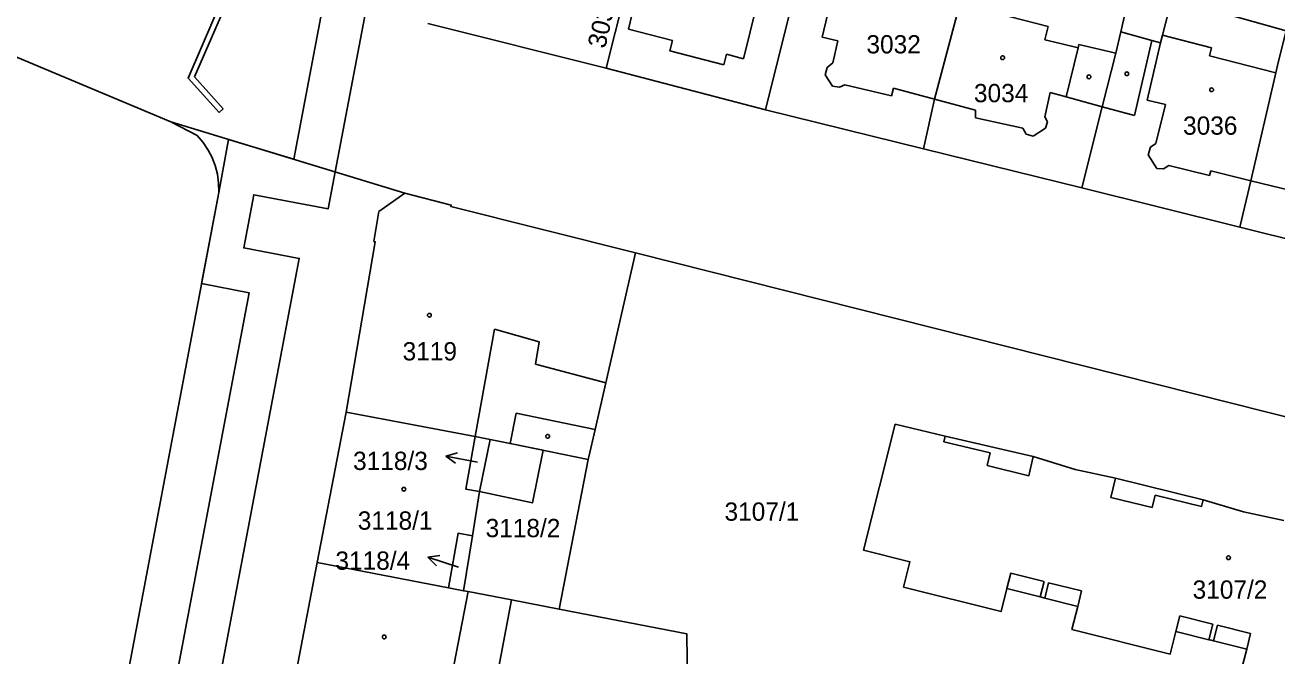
# Model space of a CAD drawing. Extents: x -756746 to -753363, y -1166406 to -1161727.
# Drawn here: x -755238.8 to -755122.4, y -1165407.1 to -1165348.4 of the extents above; entities that cross this region are included whole.
import ezdxf

# ---------------------------------------------------------------- set-up
doc = ezdxf.new("R2010")
doc.units = 0
for name, color, linetype in [('Hranice parcel', 7, 'Continuous'), ('Parcelní čísla', 7, 'Continuous'), ('Pop  PČ popisy', 7, 'Continuous'), ('Vnitřní kresba', 7, 'Continuous'), ('Věcná břemena k části', 7, 'Continuous'), ('Značky budov', 7, 'Continuous')]:
    doc.layers.add(name, color=color, linetype=linetype)

msp = doc.modelspace()

# ---------------------------------------------------------------- linework, layer by layer
at = {"layer": 'Hranice parcel'}
for p, q in [((-755287.52, -1165331.34), (-755225.27, -1165357.44)), ((-755184.78, -1165352.45), (-755180.27, -1165334.69)), ((-755136.91, -1165349.06), (-755136.02, -1165345.27)), ((-755201.37, -1165348.31), (-755184.78, -1165352.45)), ((-755184.78, -1165352.45), (-755169.95, -1165356.34)), ((-755169.95, -1165356.34), (-755155.26, -1165359.95)), ((-755203.5, -1165364.07), (-755225.27, -1165357.44)), ((-755225.27, -1165357.44), (-755222.8, -1165358.71)), ((-755155.26, -1165359.95), (-755140.53, -1165363.57)), ((-755220.8, -1165364.01), (-755235.29, -1165440.63)), ((-755140.53, -1165363.57), (-755125.82, -1165367.24)), ((-755125.82, -1165367.24), (-755111.07, -1165370.94)), ((-755067.44, -1165398.51), (-755182.05, -1165369.63)), ((-755211.66, -1165398.42), (-755208.96, -1165384.45)), ((-755208.96, -1165384.45), (-755196.95, -1165386.71)), ((-755196.95, -1165386.71), (-755195.56, -1165386.99)), ((-755195.56, -1165386.99), (-755196.55, -1165391.83)), ((-755153.23, -1165386.66), (-755145.04, -1165388.58)), ((-755186.44, -1165388.84), (-755189.13, -1165402.77)), ((-755137.4, -1165390.57), (-755129.23, -1165392.58)), ((-755197.2, -1165395.95), (-755196.55, -1165391.83)), ((-755197.2, -1165395.95), (-755198.03, -1165401.05)), ((-755211.66, -1165398.42), (-755214.3, -1165412.31)), ((-755199.44, -1165400.78), (-755211.66, -1165398.42)), ((-755198.03, -1165401.05), (-755199.44, -1165400.78)), ((-755196.19, -1165415.73), (-755193.58, -1165401.91)), ((-755189.13, -1165402.77), (-755193.58, -1165401.91))]:
    msp.add_line(p, q, dxfattribs=at)
for points in [[(-755155.26, -1165359.95), (-755154.24, -1165355.34), (-755151.87, -1165346.47), (-755151.6, -1165345.43), (-755150.66, -1165341.53)], [(-755121.51, -1165348.98), (-755132.14, -1165345.97), (-755133.02, -1165349.37), (-755133.22, -1165350.11), (-755134.01, -1165349.88), (-755136.91, -1165349.06)], [(-755169.95, -1165356.34), (-755167.78, -1165347.62), (-755167.55, -1165346.71)], [(-755140.53, -1165363.57), (-755138.62, -1165356.06), (-755137.35, -1165351.07), (-755136.91, -1165349.06)], [(-755125.82, -1165367.24), (-755124.82, -1165362.92), (-755122.49, -1165352.89), (-755122.26, -1165351.91), (-755121.51, -1165348.98)], [(-755222.8, -1165358.71), (-755222.25, -1165359.36), (-755221.78, -1165360.07), (-755221.45, -1165360.7), (-755221.14, -1165361.49), (-755220.93, -1165362.32), (-755220.82, -1165363.16), (-755220.8, -1165364.01)], [(-755203.5, -1165364.07), (-755205.9, -1165365.79), (-755206.39, -1165368.56), (-755206.24, -1165368.59), (-755208.96, -1165384.45)], [(-755182.05, -1165369.63), (-755199.21, -1165365.32), (-755199.18, -1165365.18), (-755203.5, -1165364.07)], [(-755182.05, -1165369.63), (-755184.81, -1165381.71), (-755185.8, -1165386.05), (-755186.39, -1165388.6), (-755186.44, -1165388.84)], [(-755147.5, -1165400.85), (-755148.04, -1165402.99), (-755157.11, -1165400.71), (-755156.52, -1165398.36), (-755160.83, -1165397.28), (-755157.88, -1165385.57), (-755153.23, -1165386.66)], [(-755196.55, -1165391.83), (-755197.82, -1165391.61), (-755196.95, -1165386.71)], [(-755195.56, -1165386.99), (-755193.71, -1165387.37), (-755186.44, -1165388.84)], [(-755145.04, -1165388.58), (-755141.16, -1165389.76), (-755137.4, -1165390.57)], [(-755129.23, -1165392.58), (-755125.48, -1165393.7), (-755121.74, -1165394.52)], [(-755199.44, -1165400.78), (-755198.54, -1165395.71), (-755197.2, -1165395.95)], [(-755193.58, -1165401.91), (-755197.6, -1165401.13), (-755198.03, -1165401.05)], [(-755140.91, -1165402.53), (-755143.98, -1165401.75), (-755144.19, -1165401.69), (-755144.39, -1165401.63), (-755147.5, -1165400.85)], [(-755189.13, -1165402.77), (-755177.26, -1165405.07), (-755177.17, -1165412.37)], [(-755131.77, -1165404.84), (-755132.3, -1165406.94), (-755141.44, -1165404.64), (-755140.91, -1165402.53)], [(-755125.19, -1165406.48), (-755128.29, -1165405.7), (-755128.49, -1165405.66), (-755128.7, -1165405.6), (-755131.77, -1165404.84)], [(-755116.11, -1165408.75), (-755116.64, -1165410.87), (-755125.72, -1165408.59), (-755125.19, -1165406.48)]]:
    msp.add_lwpolyline(points, dxfattribs=at)
at = {"layer": 'Pop  PČ popisy'}
for p, q in [((-755199.67, -1165388.52), (-755198.59, -1165388.22)), ((-755196.72, -1165389.09), (-755199.67, -1165388.52)), ((-755199.67, -1165388.52), (-755198.78, -1165389.2)), ((-755201.35, -1165397.93), (-755200.25, -1165397.77)), ((-755198.5, -1165398.86), (-755201.35, -1165397.93)), ((-755201.35, -1165397.93), (-755200.56, -1165398.72))]:
    msp.add_line(p, q, dxfattribs=at)
at = {"layer": 'Vnitřní kresba'}
for p, q in [((-755179.86, -1165337.08), (-755182.7, -1165348.82)), ((-755171.99, -1165351.57), (-755170.74, -1165346.56)), ((-755143.67, -1165348.57), (-755151.87, -1165346.47)), ((-755164.17, -1165347.48), (-755164.67, -1165349.56)), ((-755182.7, -1165348.82), (-755178.6, -1165349.87)), ((-755143.96, -1165349.82), (-755143.67, -1165348.57)), ((-755178.6, -1165349.87), (-755178.85, -1165350.84)), ((-755164.67, -1165349.56), (-755163.21, -1165349.92)), ((-755163.21, -1165349.92), (-755163.7, -1165351.95)), ((-755142.51, -1165350.17), (-755143.96, -1165349.82)), ((-755135.62, -1165356.84), (-755134.01, -1165349.88)), ((-755133.22, -1165350.11), (-755134.45, -1165355.42)), ((-755128.47, -1165350.55), (-755133.02, -1165349.37)), ((-755178.85, -1165350.84), (-755173.81, -1165352.13)), ((-755173.81, -1165352.13), (-755173.56, -1165351.16)), ((-755173.56, -1165351.16), (-755171.99, -1165351.57)), ((-755140.87, -1165350.55), (-755142.51, -1165350.17)), ((-755141.98, -1165355.13), (-755140.87, -1165350.55)), ((-755140.87, -1165350.55), (-755140.8, -1165350.26)), ((-755140.8, -1165350.26), (-755137.35, -1165351.07)), ((-755128.66, -1165351.29), (-755128.47, -1165350.55)), ((-755164.22, -1165352.39), (-755164.4, -1165353.07)), ((-755163.7, -1165351.95), (-755164.22, -1165352.39)), ((-755122.49, -1165352.89), (-755128.66, -1165351.29)), ((-755164.4, -1165353.07), (-755163.72, -1165354.14)), ((-755163.72, -1165354.14), (-755163.07, -1165354.23)), ((-755163.07, -1165354.23), (-755162.56, -1165354.01)), ((-755162.56, -1165354.01), (-755158.24, -1165355.02)), ((-755158.24, -1165355.02), (-755158.05, -1165354.32)), ((-755158.05, -1165354.32), (-755154.24, -1165355.34)), ((-755143.97, -1165356.99), (-755143.48, -1165354.71)), ((-755143.48, -1165354.71), (-755141.98, -1165355.13)), ((-755154.24, -1165355.34), (-755150.43, -1165356.36)), ((-755141.98, -1165355.13), (-755138.62, -1165356.06)), ((-755134.45, -1165355.42), (-755132.74, -1165355.84)), ((-755132.74, -1165355.84), (-755133.63, -1165359.47)), ((-755150.43, -1165356.36), (-755150.4, -1165357.07)), ((-755150.4, -1165357.07), (-755146, -1165358.03)), ((-755143.72, -1165357.45), (-755143.97, -1165356.99)), ((-755138.62, -1165356.06), (-755135.62, -1165356.84)), ((-755146, -1165358.03), (-755145.69, -1165358.58)), ((-755145.05, -1165358.79), (-755143.89, -1165358.04)), ((-755143.89, -1165358.04), (-755143.72, -1165357.45)), ((-755145.69, -1165358.58), (-755145.05, -1165358.79)), ((-755134.14, -1165359.79), (-755134.35, -1165360.5)), ((-755134.35, -1165360.5), (-755133.56, -1165361.77)), ((-755133.63, -1165359.47), (-755134.14, -1165359.79)), ((-755132.94, -1165361.82), (-755132.44, -1165361.51)), ((-755132.44, -1165361.51), (-755128.65, -1165362.44)), ((-755133.56, -1165361.77), (-755132.94, -1165361.82)), ((-755128.65, -1165362.44), (-755128.54, -1165362)), ((-755128.54, -1165362), (-755124.82, -1165362.92)), ((-755124.82, -1165362.92), (-755120.97, -1165363.87)), ((-755196.95, -1165386.71), (-755195.16, -1165376.71)), ((-755195.16, -1165376.71), (-755190.99, -1165377.9)), ((-755190.99, -1165377.9), (-755191.33, -1165379.97)), ((-755191.33, -1165379.97), (-755184.81, -1165381.71)), ((-755193.71, -1165387.37), (-755193.14, -1165384.55)), ((-755193.14, -1165384.55), (-755185.8, -1165386.05)), ((-755153.23, -1165386.66), (-755153.36, -1165387.2)), ((-755153.36, -1165387.2), (-755149.04, -1165388.21)), ((-755149.04, -1165388.21), (-755149.32, -1165389.39)), ((-755149.32, -1165389.39), (-755145.46, -1165390.35)), ((-755145.46, -1165390.35), (-755145.04, -1165388.58)), ((-755137.4, -1165390.57), (-755137.84, -1165392.37)), ((-755137.84, -1165392.37), (-755133.98, -1165393.31)), ((-755133.98, -1165393.31), (-755133.69, -1165392.15)), ((-755133.69, -1165392.15), (-755129.38, -1165393.21)), ((-755129.38, -1165393.21), (-755129.23, -1165392.58)), ((-755147.5, -1165400.85), (-755147.14, -1165399.4)), ((-755147.14, -1165399.4), (-755144.03, -1165400.18)), ((-755144.03, -1165400.18), (-755144.39, -1165401.63)), ((-755200.27, -1165414.96), (-755197.6, -1165401.13)), ((-755143.98, -1165401.75), (-755143.62, -1165400.3)), ((-755143.62, -1165400.3), (-755140.55, -1165401.07)), ((-755140.55, -1165401.07), (-755140.91, -1165402.53)), ((-755131.77, -1165404.84), (-755131.41, -1165403.39)), ((-755131.41, -1165403.39), (-755128.34, -1165404.16)), ((-755128.34, -1165404.16), (-755128.7, -1165405.6)), ((-755128.29, -1165405.7), (-755127.92, -1165404.25)), ((-755127.92, -1165404.25), (-755124.83, -1165405.03)), ((-755124.83, -1165405.03), (-755125.19, -1165406.48))]:
    msp.add_line(p, q, dxfattribs=at)
at = {"layer": 'Věcná břemena k části'}
for points in [[(-755228.32, -1165449.49), (-755213.31, -1165370.15), (-755218.48, -1165369.17), (-755217.54, -1165364.22), (-755210.64, -1165365.54), (-755209.98, -1165362.1), (-755207, -1165346.46), (-755205.03, -1165336.11), (-755203.87, -1165319.3), (-755189.72, -1165244.55), (-755197.15, -1165243.25), (-755218.65, -1165239.5), (-755234.49, -1165236.74), (-755235.64, -1165243.85)], [(-755231.7, -1165244.55), (-755231.19, -1165241.37), (-755218.9, -1165243.52), (-755197.89, -1165247.18), (-755194.42, -1165247.79), (-755207.85, -1165318.86), (-755209, -1165335.59), (-755210.83, -1165345.21), (-755213.83, -1165360.92), (-755219.88, -1165359.08), (-755220.8, -1165364.01), (-755222.4, -1165372.49), (-755217.98, -1165373.33), (-755233, -1165452.71)]]:
    msp.add_lwpolyline(points, dxfattribs=at)
for points in [[(-755223.07, -1165353.27), (-755219.6, -1165345.25), (-755219.35, -1165342.2), (-755219.84, -1165342), (-755220.1, -1165345.13), (-755223.65, -1165353.37), (-755220.77, -1165356.57), (-755220.4, -1165356.24)], [(-755196.55, -1165391.83), (-755191.62, -1165392.88), (-755190.63, -1165387.99), (-755193.71, -1165387.37), (-755195.56, -1165386.99)]]:
    msp.add_lwpolyline(points, close=True, dxfattribs=at)
at = {"layer": 'Značky budov'}
for centre in [(-755147.89, -1165351.48), (-755139.86, -1165353.26), (-755136.33, -1165352.97), (-755128.45, -1165354.46), (-755201.21, -1165375.43), (-755190.21, -1165386.69), (-755203.59, -1165391.61), (-755126.88, -1165397.98), (-755205.41, -1165405.35)]:
    msp.add_circle(centre, 0.175, dxfattribs=at)

# ---------------------------------------------------------------- texts
at = {"layer": 'Parcelní čísla'}
msp.add_text('3030/2', height=1.7, rotation=77, dxfattribs=at).set_placement((-755184.86, -1165350.69))
for s, p in [('3032', (-755160.56, -1165351.08)), ('3034', (-755150.56, -1165355.62)), ('3036', (-755131.11, -1165358.64)), ('3119', (-755203.7, -1165379.63)), ('3118/3', (-755208.31, -1165389.82)), ('3107/1', (-755173.76, -1165394.54)), ('3118/1', (-755207.87, -1165395.37)), ('3118/2', (-755195.98, -1165396.07)), ('3118/4', (-755209.95, -1165399.1)), ('3107/2', (-755130.22, -1165401.79))]:
    msp.add_text(s, height=1.7, dxfattribs=at).set_placement(p)

doc.saveas('drawing.dxf')
